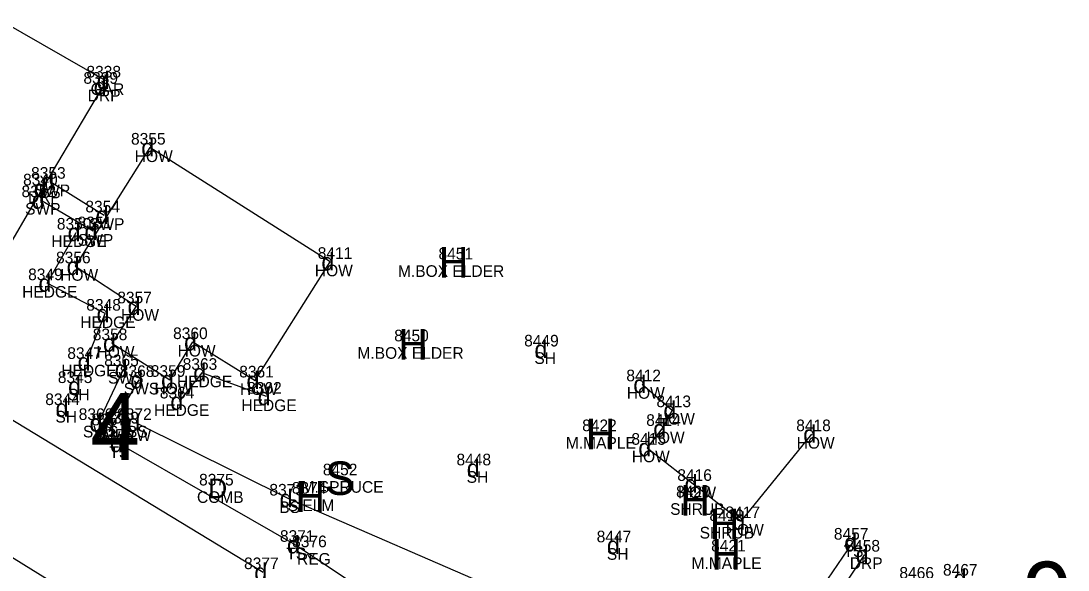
# Model space of a CAD drawing. Extents: x 69415 to 80913, y 7576 to 15059.
# Drawn here: x 77426.5 to 77606.6, y 13356.8 to 13451.2 of the extents above; entities that cross this region are included whole.
import ezdxf

# ---------------------------------------------------------------- set-up
doc = ezdxf.new("R2010")
doc.units = 0
for name, color, linetype in [('Level 11', 7, 'Continuous'), ('Level 12', 7, 'Continuous'), ('Level 13', 7, 'Continuous'), ('Level 14', 7, 'Continuous'), ('Level 15', 7, 'Continuous'), ('Level 43', 7, 'Continuous'), ('Level 46', 7, 'Continuous'), ('Level 47', 7, 'Continuous'), ('Level 48', 7, 'Continuous')]:
    doc.layers.add(name, color=color, linetype=linetype)

msp = doc.modelspace()

# ---------------------------------------------------------------- linework, layer by layer
at = {"layer": 'Level 11'}
for p, q in [((77440.5, 13439.94), (77430.2, 13422.46)), ((77430.2, 13422.46), (77413.74, 13394.34)), ((77412.97, 13389.9), (77468.14, 13356.46)), ((77571.61, 13359.48), (77555.07, 13334.36))]:
    msp.add_line(p, q, dxfattribs=at)
at = {"layer": 'Level 12'}
for p, q in [((77431.5, 13423.61), (77440.84, 13417.82)), ((77438.92, 13415.09), (77429.85, 13420.44)), ((77444.12, 13391.37), (77439.79, 13382.12)), ((77441.94, 13381.19), (77446.81, 13389.51)), ((77439.79, 13382.12), (77441.94, 13381.19))]:
    msp.add_line(p, q, dxfattribs=at)
at = {"layer": 'Level 13'}
for p, q in [((77423.13, 13451.25), (77441.02, 13441.02)), ((77448.69, 13429.48), (77435.85, 13409.06)), ((77479.68, 13409.83), (77448.69, 13429.48)), ((77435.85, 13409.06), (77446.33, 13402.18)), ((77466.79, 13389.43), (77479.68, 13409.83)), ((77446.33, 13402.18), (77442.11, 13395.84)), ((77442.11, 13395.84), (77452.1, 13389.54)), ((77452.1, 13389.54), (77456.06, 13396.03)), ((77456.06, 13396.03), (77466.79, 13389.43)), ((77533.35, 13388.77), (77538.52, 13384.32)), ((77538.52, 13384.32), (77536.77, 13381.1)), ((77536.77, 13381.1), (77534.21, 13377.85)), ((77550.39, 13365.23), (77562.58, 13380.19)), ((77534.21, 13377.85), (77542.17, 13371.64)), ((77542.17, 13371.64), (77550.39, 13365.23))]:
    msp.add_line(p, q, dxfattribs=at)
at = {"layer": 'Level 14'}
for p, q in [((77431, 13406.16), (77436.02, 13414.86)), ((77441, 13400.92), (77431, 13406.16)), ((77437.73, 13392.62), (77441, 13400.92)), ((77457.63, 13390.74), (77453.69, 13385.82)), ((77468.72, 13386.64), (77457.63, 13390.74))]:
    msp.add_line(p, q, dxfattribs=at)
at = {"layer": 'Level 48'}
for p, q in [((77446.3, 13382.12), (77472.5, 13369.12)), ((77443.31, 13378.57), (77473.75, 13361.16)), ((77472.5, 13369.12), (77518.59, 13349.16)), ((77418.14, 13363.22), (77460.95, 13336.81)), ((77473.75, 13361.16), (77510.28, 13336.84)), ((77541.15, 13319.79), (77569.62, 13361.54))]:
    msp.add_line(p, q, dxfattribs=at)

# ---------------------------------------------------------------- texts
at = {"layer": 'Level 14'}
for s, height, p in [('H', 5.3, (77498.37, 13407.08)), ('H', 5.3, (77491.4, 13392.99)), ('H', 5.3, (77523.66, 13377.54)), ('S', 5.75, (77478.81, 13369.73)), ('H', 5.3, (77473.71, 13366.8)), ('H', 5.3, (77539.91, 13366.15)), ('H', 5.3, (77544.99, 13362.08)), ('H', 5.3, (77545.28, 13356.85))]:
    msp.add_text(s, height=height, dxfattribs=at).set_placement(p)
at = {"layer": 'Level 15'}
for s, height, p in [('4', 11.5, (77438.43, 13375.76)), ('D', 3.4, (77458.7, 13369.15)), ('9', 11.5, (77598.83, 13346.74))]:
    msp.add_text(s, height=height, dxfattribs=at).set_placement(p)
at = {"layer": 'Level 43'}
msp.add_text('Y', height=1.7, dxfattribs=at).set_placement((77475.61, 13357.88))
at = {"layer": 'Level 46'}
for s, p in [('8338', (77437.76, 13441.52)), ('8339', (77437.24, 13440.44)), ('GAR', (77438.48, 13438.52)), ('DRP', (77437.99, 13437.44)), ('8355', (77445.43, 13429.98)), ('HOW', (77446.07, 13426.98)), ('8353', (77428.24, 13424.11)), ('8340', (77426.86, 13422.96)), ('8352', (77426.59, 13420.94)), ('DRP', (77427.69, 13419.96)), ('SWP', (77428.86, 13421.11)), ('SWP', (77427.21, 13417.94)), ('8354', (77437.58, 13418.32)), ('8350', (77432.67, 13415.36)), ('8351', (77436.23, 13415.59)), ('SWP', (77438.21, 13415.32)), ('SWP', (77436.29, 13412.59)), ('HEDGE', (77431.72, 13412.36)), ('8356', (77432.53, 13409.56)), ('8411', (77477.55, 13410.33)), ('8451', (77498.33, 13410.23)), ('HOW', (77477.06, 13407.33)), ('M.BOX ELDER', (77491.36, 13407.23)), ('8349', (77427.73, 13406.66)), ('HOW', (77433.24, 13406.56)), ('HEDGE', (77426.7, 13403.66)), ('8357', (77443.07, 13402.68)), ('8348', (77437.74, 13401.42)), ('HEDGE', (77436.7, 13398.42)), ('HOW', (77443.71, 13399.68)), ('8358', (77438.85, 13396.34)), ('8360', (77452.67, 13396.53)), ('8450', (77490.71, 13396.14)), ('8449', (77513.07, 13395.26)), ('8347', (77434.47, 13393.12)), ('HOW', (77439.5, 13393.34)), ('HOW', (77453.45, 13393.53)), ('M.BOX ELDER', (77484.39, 13393.14)), ('8365', (77440.82, 13391.87)), ('8363', (77454.32, 13391.24)), ('SH', (77514.83, 13392.26)), ('HEDGE', (77433.43, 13390.12)), ('8368', (77443.5, 13390.01)), ('8359', (77448.83, 13390.04)), ('8361', (77464.05, 13389.93)), ('8412', (77530.65, 13389.27)), ('8345', (77432.84, 13388.97)), ('SWS', (77441.49, 13388.87)), ('HEDGE', (77453.33, 13388.24)), ('SH', (77434.59, 13385.97)), ('SWS', (77444.18, 13387.01)), ('HOW', (77449.48, 13387.04)), ('8364', (77450.38, 13386.32)), ('HOW', (77464.17, 13386.93)), ('8362', (77465.41, 13387.14)), ('HOW', (77530.73, 13386.27)), ('8344', (77430.68, 13385.18)), ('HEDGE', (77464.42, 13384.14)), ('8413', (77535.83, 13384.82)), ('SH', (77432.43, 13382.18)), ('8366', (77436.43, 13382.62)), ('8369', (77440.87, 13382.01)), ('8372', (77443.04, 13382.62)), ('HEDGE', (77449.39, 13383.32)), ('HOW', (77535.91, 13381.82)), ('8367', (77438.63, 13381.69)), ('8422', (77523.05, 13380.69)), ('8414', (77534.07, 13381.6)), ('8418', (77559.88, 13380.69)), ('SWS', (77437.16, 13379.62)), ('SWS', (77439.31, 13378.69)), ('8370', (77439.97, 13379.07)), ('GUYW', (77440.58, 13379.01)), ('BS', (77444.74, 13379.62)), ('8415', (77531.52, 13378.35)), ('HOW', (77534.15, 13378.6)), ('M.MAPLE', (77520.25, 13377.69)), ('HOW', (77559.96, 13377.69)), ('TS', (77441.72, 13376.07)), ('8448', (77501.43, 13374.81)), ('HOW', (77531.59, 13375.35)), ('8452', (77478.43, 13373.1)), ('8375', (77457.14, 13371.35)), ('SH', (77503.18, 13371.81)), ('8416', (77539.42, 13372.14)), ('8373', (77469.24, 13369.62)), ('8374', (77473.1, 13369.94)), ('M.SPRUCE', (77474.77, 13370.1)), ('8420', (77539.21, 13369.3)), ('COMB', (77456.78, 13368.35)), ('HOW', (77539.55, 13369.14)), ('BS', (77470.94, 13366.62)), ('S.ELM', (77472.39, 13366.94)), ('SHRUB', (77538.19, 13366.3)), ('8417', (77547.7, 13365.73)), ('8419', (77544.94, 13365.23)), ('SHRUB', (77543.27, 13362.23)), ('HOW', (77547.77, 13362.73)), ('8457', (77566.36, 13362.04)), ('8371', (77471.05, 13361.66)), ('8376', (77473.15, 13360.73)), ('8447', (77525.55, 13361.57)), ('TS', (77472.16, 13358.66)), ('SH', (77527.3, 13358.57)), ('8421', (77545.24, 13360)), ('TS', (77568.03, 13359.04)), ('8458', (77568.35, 13359.98)), ('8377', (77464.88, 13356.96)), ('REG', (77474, 13357.73)), ('M.MAPLE', (77541.87, 13357)), ('DRP', (77569.1, 13356.98)), ('8466', (77577.63, 13355.33)), ('8467', (77585.13, 13355.85))]:
    msp.add_text(s, height=2, dxfattribs=at).set_placement(p)
at = {"layer": 'Level 47'}
for p in [(77439, 13438.44), (77439.52, 13439.52), (77447.19, 13427.98), (77430, 13422.11), (77428.7, 13420.96), (77428.35, 13418.94), (77439.34, 13416.32), (77434.52, 13413.36), (77437.42, 13413.59), (77478.18, 13408.33), (77434.35, 13407.56), (77429.5, 13404.66), (77444.83, 13400.68), (77439.5, 13399.42), (77440.61, 13394.34), (77454.56, 13394.53), (77514.84, 13393.26), (77436.23, 13391.12), (77442.62, 13389.87), (77445.31, 13388.01), (77450.6, 13388.04), (77456.13, 13389.24), (77465.29, 13387.93), (77434.6, 13386.97), (77531.85, 13387.27), (77452.19, 13384.32), (77467.22, 13385.14), (77432.44, 13383.18), (77537.02, 13382.82), (77438.29, 13380.62), (77440.44, 13379.69), (77444.8, 13380.62), (77535.27, 13379.6), (77441.81, 13377.07), (77561.08, 13378.69), (77532.71, 13376.35), (77503.19, 13372.81), (77540.67, 13370.14), (77471, 13367.62), (77548.89, 13363.73), (77472.25, 13359.66), (77527.31, 13359.57), (77568.12, 13360.04), (77570.11, 13357.98), (77466.64, 13354.96), (77586.94, 13353.85)]:
    msp.add_text('d', height=3, dxfattribs=at).set_placement(p)

doc.saveas('drawing.dxf')
